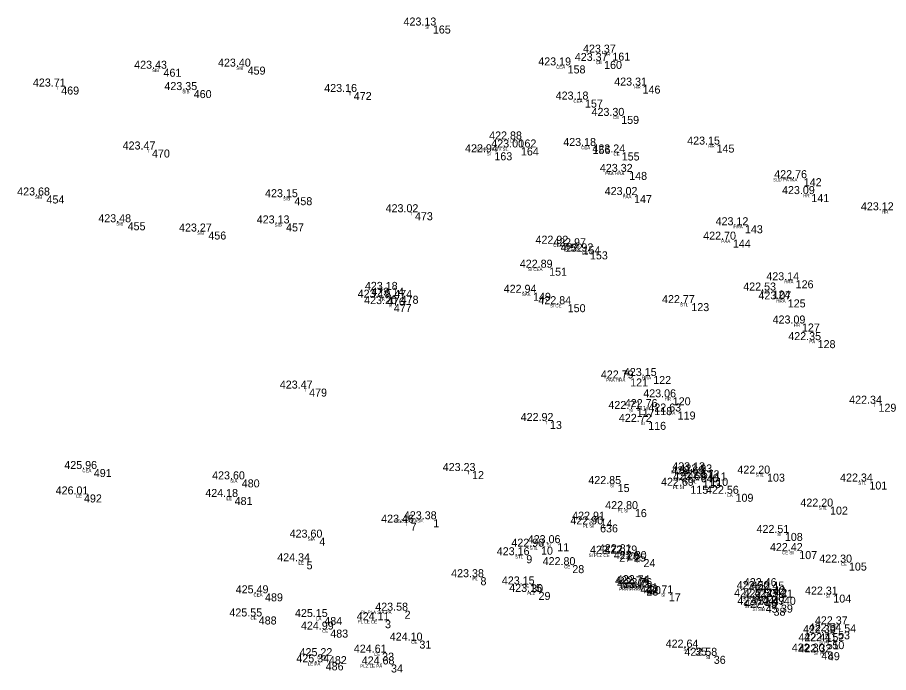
# Model space of a CAD drawing. Extents: x -639373 to -639057, y -1138651 to -1138359.
# Drawn here: x -639183 to -639101.4, y -1138650.6 to -1138589.2 of the extents above; entities that cross this region are included whole.
import ezdxf

# ---------------------------------------------------------------- set-up
doc = ezdxf.new("R2010")
doc.units = 0
for name, color, linetype in [('Vrstva 11', 7, 'Continuous'), ('Vrstva 12', 7, 'Continuous'), ('Vrstva 13', 7, 'Continuous'), ('Vrstva 14', 7, 'Continuous'), ('Vrstva 57', 7, 'Continuous')]:
    doc.layers.add(name, color=color, linetype=linetype)

msp = doc.modelspace()

# ---------------------------------------------------------------- linework, layer by layer
at = {"layer": 'Vrstva 11'}
for p, q in [((-639144.39, -1138589.97), (-639144.39, -1138589.97)), ((-639127.58, -1138592.51), (-639127.58, -1138592.51)), ((-639161.74, -1138593.82), (-639161.74, -1138593.82)), ((-639131.77, -1138593.71), (-639131.77, -1138593.71)), ((-639128.35, -1138593.29), (-639128.35, -1138593.29)), ((-639169.62, -1138594.02), (-639169.62, -1138594.02)), ((-639179.2, -1138595.69), (-639179.2, -1138595.69)), ((-639166.79, -1138596.02), (-639166.79, -1138596.02)), ((-639151.8, -1138596.2), (-639151.8, -1138596.2)), ((-639124.75, -1138595.6), (-639124.75, -1138595.6)), ((-639130.14, -1138596.91), (-639130.14, -1138596.91)), ((-639126.75, -1138598.44), (-639126.75, -1138598.44)), ((-639136.37, -1138600.65), (-639136.37, -1138600.65)), ((-639117.82, -1138601.13), (-639117.82, -1138601.13)), ((-639170.7, -1138601.59), (-639170.7, -1138601.59)), ((-639138.63, -1138601.85), (-639138.63, -1138601.85)), ((-639136.14, -1138601.4), (-639136.14, -1138601.4)), ((-639129.43, -1138601.26), (-639129.43, -1138601.26)), ((-639126.7, -1138601.87), (-639126.7, -1138601.87)), ((-639126, -1138603.69), (-639126, -1138603.69)), ((-639109.65, -1138604.28), (-639109.65, -1138604.28)), ((-639180.58, -1138605.9), (-639180.58, -1138605.9)), ((-639157.36, -1138606.06), (-639157.36, -1138606.06)), ((-639125.55, -1138605.86), (-639125.55, -1138605.86)), ((-639108.94, -1138605.77), (-639108.94, -1138605.77)), ((-639146.07, -1138607.47), (-639146.07, -1138607.47)), ((-639101.55, -1138607.29), (-639101.55, -1138607.29)), ((-639172.98, -1138608.41), (-639172.98, -1138608.41)), ((-639158.14, -1138608.52), (-639158.14, -1138608.52)), ((-639165.42, -1138609.28), (-639165.42, -1138609.28)), ((-639115.16, -1138608.69), (-639115.16, -1138608.69)), ((-639116.29, -1138610.04), (-639116.29, -1138610.04)), ((-639132.03, -1138610.42), (-639132.03, -1138610.42)), ((-639130.37, -1138610.66), (-639130.37, -1138610.66)), ((-639129.68, -1138611.14), (-639129.68, -1138611.14)), ((-639133.5, -1138612.67), (-639133.5, -1138612.67)), ((-639110.41, -1138613.85), (-639110.41, -1138613.85)), ((-639148.01, -1138614.75), (-639148.01, -1138614.75)), ((-639135.01, -1138615.02), (-639135.01, -1138615.02)), ((-639112.57, -1138614.81), (-639112.57, -1138614.81)), ((-639148.69, -1138615.48), (-639148.69, -1138615.48)), ((-639147.41, -1138615.3), (-639147.41, -1138615.3)), ((-639111.15, -1138615.64), (-639111.15, -1138615.64)), ((-639148.05, -1138616.08), (-639148.05, -1138616.08)), ((-639131.76, -1138616.09), (-639131.76, -1138616.09)), ((-639120.18, -1138615.99), (-639120.18, -1138615.99)), ((-639109.82, -1138617.9), (-639109.82, -1138617.9)), ((-639108.35, -1138619.46), (-639108.35, -1138619.46)), ((-639125.91, -1138623.05), (-639125.91, -1138623.05)), ((-639123.75, -1138622.82), (-639123.75, -1138622.82)), ((-639155.98, -1138624), (-639155.98, -1138624)), ((-639121.92, -1138624.82), (-639121.92, -1138624.82)), ((-639102.65, -1138625.42), (-639102.65, -1138625.42)), ((-639125.3, -1138625.91), (-639125.3, -1138625.91)), ((-639123.65, -1138625.74), (-639123.65, -1138625.74)), ((-639121.46, -1138626.15), (-639121.46, -1138626.15)), ((-639133.42, -1138627.04), (-639133.42, -1138627.04)), ((-639124.22, -1138627.12), (-639124.22, -1138627.12)), ((-639176.15, -1138631.54), (-639176.15, -1138631.54)), ((-639140.72, -1138631.73), (-639140.72, -1138631.73)), ((-639119.3, -1138632.04), (-639119.3, -1138632.04)), ((-639119.22, -1138631.66), (-639119.22, -1138631.66)), ((-639118.55, -1138631.86), (-639118.55, -1138631.86)), ((-639113.09, -1138631.97), (-639113.09, -1138631.97)), ((-639162.29, -1138632.51), (-639162.29, -1138632.51)), ((-639127.08, -1138632.95), (-639127.08, -1138632.95)), ((-639119.12, -1138632.58), (-639119.12, -1138632.58)), ((-639118.41, -1138632.37), (-639118.41, -1138632.37)), ((-639103.5, -1138632.71), (-639103.5, -1138632.71)), ((-639120.27, -1138633.11), (-639120.27, -1138633.11)), ((-639116.04, -1138633.86), (-639116.04, -1138633.86)), ((-639177.07, -1138633.92), (-639177.07, -1138633.92)), ((-639162.96, -1138634.16), (-639162.96, -1138634.16)), ((-639125.47, -1138635.3), (-639125.47, -1138635.3)), ((-639107.19, -1138635.06), (-639107.19, -1138635.06)), ((-639144.36, -1138636.25), (-639144.36, -1138636.25)), ((-639128.69, -1138636.29), (-639128.69, -1138636.29)), ((-639146.47, -1138636.57), (-639146.47, -1138636.57)), ((-639128.73, -1138636.73), (-639128.73, -1138636.73)), ((-639111.42, -1138637.53), (-639111.42, -1138637.53)), ((-639155.03, -1138637.97), (-639155.03, -1138637.97)), ((-639132.74, -1138638.49), (-639132.74, -1138638.49)), ((-639134.26, -1138638.82), (-639134.26, -1138638.82)), ((-639126.93, -1138639.48), (-639126.93, -1138639.48)), ((-639126.19, -1138639.34), (-639126.19, -1138639.34)), ((-639125.57, -1138639.46), (-639125.57, -1138639.46)), ((-639110.07, -1138639.23), (-639110.07, -1138639.23)), ((-639156.22, -1138640.19), (-639156.22, -1138640.19)), ((-639135.64, -1138639.62), (-639135.64, -1138639.62)), ((-639124.66, -1138639.98), (-639124.66, -1138639.98)), ((-639105.42, -1138640.31), (-639105.42, -1138640.31)), ((-639131.33, -1138640.55), (-639131.33, -1138640.55)), ((-639139.93, -1138641.68), (-639139.93, -1138641.68)), ((-639135.18, -1138642.36), (-639135.18, -1138642.36)), ((-639124.58, -1138642.35), (-639124.58, -1138642.35)), ((-639124.41, -1138642.24), (-639124.41, -1138642.24)), ((-639124.39, -1138642.65), (-639124.39, -1138642.65)), ((-639124.15, -1138642.52), (-639124.15, -1138642.52)), ((-639113.16, -1138642.8), (-639113.16, -1138642.8)), ((-639112.5, -1138642.52), (-639112.5, -1138642.52)), ((-639111.79, -1138642.84), (-639111.79, -1138642.84)), ((-639160.11, -1138643.19), (-639160.11, -1138643.19)), ((-639134.49, -1138643.06), (-639134.49, -1138643.06)), ((-639122.29, -1138643.19), (-639122.29, -1138643.19)), ((-639113.52, -1138643.51), (-639113.52, -1138643.51)), ((-639112.54, -1138643.55), (-639112.54, -1138643.55)), ((-639111.52, -1138643.52), (-639111.52, -1138643.52)), ((-639106.88, -1138643.31), (-639106.88, -1138643.31)), ((-639113.22, -1138644.26), (-639113.22, -1138644.26)), ((-639111.79, -1138644.25), (-639111.79, -1138644.25)), ((-639147.04, -1138644.82), (-639147.04, -1138644.82)), ((-639112.48, -1138644.54), (-639112.48, -1138644.54)), ((-639160.7, -1138645.36), (-639160.7, -1138645.36)), ((-639154.56, -1138645.41), (-639154.56, -1138645.41)), ((-639148.87, -1138645.71), (-639148.87, -1138645.71)), ((-639105.86, -1138646.1), (-639105.86, -1138646.1)), ((-639154, -1138646.59), (-639154, -1138646.59)), ((-639106.97, -1138646.92), (-639106.97, -1138646.92)), ((-639106.44, -1138646.75), (-639106.44, -1138646.75)), ((-639145.65, -1138647.62), (-639145.65, -1138647.62)), ((-639107.49, -1138647.68), (-639107.49, -1138647.68)), ((-639106.97, -1138647.67), (-639106.97, -1138647.67)), ((-639119.84, -1138648.28), (-639119.84, -1138648.28)), ((-639154.13, -1138649.08), (-639154.13, -1138649.08)), ((-639149.14, -1138648.75), (-639149.14, -1138648.75)), ((-639118.08, -1138649.05), (-639118.08, -1138649.05)), ((-639107.99, -1138648.65), (-639107.99, -1138648.65)), ((-639107.39, -1138648.71), (-639107.39, -1138648.71)), ((-639154.43, -1138649.66), (-639154.43, -1138649.66)), ((-639148.31, -1138649.86), (-639148.31, -1138649.86))]:
    msp.add_line(p, q, dxfattribs=at)

# ---------------------------------------------------------------- texts
at = {"layer": 'Vrstva 12'}
for s, p in [('422.88 ', (-639138.839, -1138600.65)), ('423.00 ', (-639138.639, -1138601.4)), ('423.32 ', (-639128.469, -1138603.69)), ('422.76 ', (-639112.136, -1138604.28)), ('423.02 ', (-639128.019, -1138605.86)), ('423.12 ', (-639117.629, -1138608.69)), ('422.70 ', (-639118.789, -1138610.04)), ('423.14 ', (-639112.879, -1138613.85)), ('422.53 ', (-639115.039, -1138614.81)), ('423.07 ', (-639113.619, -1138615.64)), ('423.09 ', (-639112.289, -1138617.9)), ('422.35 ', (-639110.82, -1138619.46)), ('422.79 ', (-639128.379, -1138623.05)), ('423.15 ', (-639126.22, -1138622.82)), ('423.06 ', (-639124.406, -1138624.82)), ('422.34 ', (-639105.119, -1138625.42)), ('422.76 ', (-639126.136, -1138625.74)), ('422.63 ', (-639123.929, -1138626.15)), ('425.96 ', (-639178.636, -1138631.54)), ('423.13 ', (-639121.689, -1138631.66)), ('422.20 ', (-639115.589, -1138631.97)), ('423.60 ', (-639164.789, -1138632.51)), ('422.34 ', (-639105.969, -1138632.71)), ('426.01 ', (-639179.445, -1138633.92)), ('424.18 ', (-639165.429, -1138634.16)), ('422.56 ', (-639118.526, -1138633.86)), ('422.20 ', (-639109.689, -1138635.06)), ('422.90 ', (-639131.229, -1138636.73)), ('422.51 ', (-639113.795, -1138637.53)), ('423.60 ', (-639157.529, -1138637.97)), ('423.06 ', (-639135.226, -1138638.49)), ('422.77 ', (-639129.399, -1138639.48)), ('422.81 ', (-639128.565, -1138639.34)), ('422.79 ', (-639128.039, -1138639.46)), ('422.42 ', (-639112.539, -1138639.23)), ('424.34 ', (-639158.689, -1138640.19)), ('422.80 ', (-639127.159, -1138639.98)), ('422.30 ', (-639107.919, -1138640.31)), ('422.80 ', (-639133.829, -1138640.55)), ('423.38 ', (-639142.399, -1138641.68)), ('423.15 ', (-639137.65, -1138642.36)), ('422.74 ', (-639127.049, -1138642.35)), ('422.74 ', (-639126.879, -1138642.24)), ('422.72 ', (-639126.859, -1138642.65)), ('422.76 ', (-639126.636, -1138642.52)), ('422.46 ', (-639114.986, -1138642.52)), ('425.49 ', (-639162.579, -1138643.19)), ('423.15 ', (-639136.96, -1138643.06)), ('422.71 ', (-639124.665, -1138643.19)), ('422.51 ', (-639115.895, -1138643.51)), ('422.50 ', (-639115.659, -1138642.8)), ('422.53 ', (-639115.009, -1138643.55)), ('422.45 ', (-639114.26, -1138642.84)), ('422.42 ', (-639113.989, -1138643.52)), ('422.31 ', (-639109.255, -1138643.31)), ('422.51 ', (-639115.595, -1138644.26)), ('422.49 ', (-639114.259, -1138644.25)), ('423.58 ', (-639149.509, -1138644.82)), ('422.45 ', (-639114.95, -1138644.54)), ('425.55 ', (-639163.17, -1138645.36)), ('425.15 ', (-639157.03, -1138645.41)), ('424.11 ', (-639151.245, -1138645.71)), ('424.99 ', (-639156.469, -1138646.59)), ('422.34 ', (-639108.909, -1138646.75)), ('422.37 ', (-639108.329, -1138646.1)), ('424.10 ', (-639148.149, -1138647.62)), ('422.41 ', (-639109.865, -1138647.68)), ('422.39 ', (-639109.439, -1138646.92)), ('422.41 ', (-639109.345, -1138647.67)), ('422.64 ', (-639122.309, -1138648.28)), ('425.22 ', (-639156.599, -1138649.08)), ('424.61 ', (-639151.515, -1138648.75)), ('422.58 ', (-639120.549, -1138649.05)), ('422.30 ', (-639110.489, -1138648.65)), ('422.32 ', (-639109.859, -1138648.71)), ('425.34 ', (-639156.899, -1138649.66)), ('424.68 ', (-639150.779, -1138649.86))]:
    msp.add_text(s, height=0.75, dxfattribs=at).set_placement(p)
at = {"layer": 'Vrstva 13'}
for s, p in [(' 165', (-639144.39, -1138590.72)), (' 161', (-639127.58, -1138593.26)), (' 459', (-639161.74, -1138594.57)), (' 158', (-639131.77, -1138594.46)), (' 160', (-639128.35, -1138594.04)), (' 461', (-639169.62, -1138594.77)), (' 469', (-639179.2, -1138596.44)), (' 460', (-639166.79, -1138596.77)), (' 472', (-639151.8, -1138596.95)), (' 146', (-639124.75, -1138596.35)), (' 157', (-639130.14, -1138597.66)), (' 159', (-639126.75, -1138599.19)), (' 162', (-639136.37, -1138601.4)), (' 145', (-639117.82, -1138601.88)), (' 470', (-639170.7, -1138602.34)), (' 163', (-639138.63, -1138602.6)), (' 164', (-639136.14, -1138602.15)), (' 156', (-639129.43, -1138602.01)), (' 155', (-639126.7, -1138602.62)), (' 148', (-639126, -1138604.44)), (' 142', (-639109.65, -1138605.03)), (' 454', (-639180.58, -1138606.65)), (' 458', (-639157.36, -1138606.81)), (' 147', (-639125.55, -1138606.61)), (' 141', (-639108.94, -1138606.52)), (' 473', (-639146.07, -1138608.22)), (' 455', (-639172.98, -1138609.16)), (' 457', (-639158.14, -1138609.27)), (' 456', (-639165.42, -1138610.03)), (' 143', (-639115.16, -1138609.44)), (' 144', (-639116.29, -1138610.79)), (' 152', (-639132.03, -1138611.17)), (' 154', (-639130.37, -1138611.41)), (' 153', (-639129.68, -1138611.89)), (' 151', (-639133.5, -1138613.42)), (' 126', (-639110.41, -1138614.6)), (' 474', (-639148.01, -1138615.5)), (' 149', (-639135.01, -1138615.77)), (' 124', (-639112.57, -1138615.56)), (' 476', (-639148.69, -1138616.23)), (' 478', (-639147.41, -1138616.05)), (' 125', (-639111.15, -1138616.39)), (' 477', (-639148.05, -1138616.83)), (' 150', (-639131.76, -1138616.84)), (' 123', (-639120.18, -1138616.74)), (' 127', (-639109.82, -1138618.65)), (' 128', (-639108.35, -1138620.21)), (' 121', (-639125.91, -1138623.8)), (' 122', (-639123.75, -1138623.57)), (' 479', (-639155.98, -1138624.75)), (' 120', (-639121.92, -1138625.57)), (' 129', (-639102.65, -1138626.17)), (' 117', (-639125.3, -1138626.66)), (' 118', (-639123.65, -1138626.49)), (' 119', (-639121.46, -1138626.9)), (' 13', (-639133.42, -1138627.79)), (' 116', (-639124.22, -1138627.87)), (' 491', (-639176.15, -1138632.29)), (' 12', (-639140.72, -1138632.48)), (' 640', (-639119.3, -1138632.79)), (' 112', (-639119.22, -1138632.41)), (' 111', (-639118.55, -1138632.61)), (' 103', (-639113.09, -1138632.72)), (' 480', (-639162.29, -1138633.26)), (' 15', (-639127.08, -1138633.7)), (' 113', (-639119.12, -1138633.33)), (' 110', (-639118.41, -1138633.12)), (' 101', (-639103.5, -1138633.46)), (' 115', (-639120.27, -1138633.86)), (' 109', (-639116.04, -1138634.61)), (' 492', (-639177.07, -1138634.67)), (' 481', (-639162.96, -1138634.91)), (' 16', (-639125.47, -1138636.05)), (' 102', (-639107.19, -1138635.81)), (' 1', (-639144.36, -1138637)), (' 14', (-639128.69, -1138637.04)), (' 7', (-639146.47, -1138637.32)), (' 636', (-639128.73, -1138637.48)), (' 108', (-639111.42, -1138638.28)), (' 4', (-639155.03, -1138638.72)), (' 11', (-639132.74, -1138639.24)), (' 10', (-639134.26, -1138639.57)), (' 27', (-639126.93, -1138640.23)), (' 26', (-639126.19, -1138640.09)), (' 25', (-639125.57, -1138640.21)), (' 107', (-639110.07, -1138639.98)), (' 5', (-639156.22, -1138640.94)), (' 9', (-639135.64, -1138640.37)), (' 24', (-639124.66, -1138640.73)), (' 105', (-639105.42, -1138641.06)), (' 28', (-639131.33, -1138641.3)), (' 8', (-639139.93, -1138642.43)), (' 30', (-639135.18, -1138643.11)), (' 22', (-639124.58, -1138643.1)), (' 21', (-639124.41, -1138642.99)), (' 23', (-639124.39, -1138643.4)), (' 20', (-639124.15, -1138643.27)), (' 43', (-639113.16, -1138643.55)), (' 42', (-639112.5, -1138643.27)), (' 41', (-639111.79, -1138643.59)), (' 489', (-639160.11, -1138643.94)), (' 29', (-639134.49, -1138643.81)), (' 17', (-639122.29, -1138643.94)), (' 44', (-639113.52, -1138644.26)), (' 47', (-639112.54, -1138644.3)), (' 40', (-639111.52, -1138644.27)), (' 104', (-639106.88, -1138644.06)), (' 45', (-639113.22, -1138645.01)), (' 39', (-639111.79, -1138645)), (' 2', (-639147.04, -1138645.57)), (' 38', (-639112.48, -1138645.29)), (' 488', (-639160.7, -1138646.11)), (' 484', (-639154.56, -1138646.16)), (' 3', (-639148.87, -1138646.46)), (' 54', (-639105.86, -1138646.85)), (' 483', (-639154, -1138647.34)), (' 52', (-639106.97, -1138647.67)), (' 53', (-639106.44, -1138647.5)), (' 31', (-639145.65, -1138648.37)), (' 51', (-639107.49, -1138648.43)), (' 50', (-639106.97, -1138648.42)), (' 35', (-639119.84, -1138649.03)), (' 482', (-639154.13, -1138649.83)), (' 33', (-639149.14, -1138649.5)), (' 36', (-639118.08, -1138649.8)), (' 48', (-639107.99, -1138649.4)), (' 49', (-639107.39, -1138649.46)), (' 486', (-639154.43, -1138650.41)), (' 34', (-639148.31, -1138650.61))]:
    msp.add_text(s, height=0.75, dxfattribs=at).set_placement(p)
at = {"layer": 'Vrstva 14'}
for s, p in [('423.13 ', (-639146.859, -1138589.97)), ('423.37 ', (-639130.049, -1138592.51)), ('423.40 ', (-639164.239, -1138593.82)), ('423.19 ', (-639134.239, -1138593.71)), ('423.37 ', (-639130.819, -1138593.29)), ('423.43 ', (-639172.089, -1138594.02)), ('423.71 ', (-639181.575, -1138595.69)), ('423.35 ', (-639169.26, -1138596.02)), ('423.16 ', (-639154.286, -1138596.2)), ('423.31 ', (-639127.125, -1138595.6)), ('423.18 ', (-639132.609, -1138596.91)), ('423.30 ', (-639129.249, -1138598.44)), ('423.15 ', (-639120.29, -1138601.13)), ('423.47 ', (-639173.169, -1138601.59)), ('422.94 ', (-639141.099, -1138601.85)), ('423.18 ', (-639131.899, -1138601.26)), ('423.24 ', (-639129.169, -1138601.87)), ('423.68 ', (-639183.049, -1138605.9)), ('423.15 ', (-639159.83, -1138606.06)), ('423.09 ', (-639111.409, -1138605.77)), ('423.02 ', (-639148.539, -1138607.47)), ('423.12 ', (-639104.019, -1138607.29)), ('423.48 ', (-639175.449, -1138608.41)), ('423.13 ', (-639160.609, -1138608.52)), ('423.27 ', (-639167.889, -1138609.28)), ('422.92 ', (-639134.499, -1138610.42)), ('422.97 ', (-639132.839, -1138610.66)), ('422.92 ', (-639132.149, -1138611.14)), ('422.89 ', (-639135.969, -1138612.67)), ('423.18 ', (-639150.479, -1138614.75)), ('422.94 ', (-639137.479, -1138615.02)), ('423.19 ', (-639151.159, -1138615.48)), ('423.14 ', (-639149.879, -1138615.3)), ('423.20 ', (-639150.549, -1138616.08)), ('422.84 ', (-639134.229, -1138616.09)), ('422.77 ', (-639122.649, -1138615.99)), ('423.47 ', (-639158.449, -1138624)), ('422.71 ', (-639127.675, -1138625.91)), ('422.92 ', (-639135.889, -1138627.04)), ('422.72 ', (-639126.689, -1138627.12)), ('423.23 ', (-639143.189, -1138631.73)), ('422.69 ', (-639121.769, -1138632.04)), ('422.93 ', (-639121.019, -1138631.86)), ('422.85 ', (-639129.55, -1138632.95)), ('422.69 ', (-639121.589, -1138632.58)), ('422.57 ', (-639120.879, -1138632.37)), ('422.69 ', (-639122.739, -1138633.11)), ('422.80 ', (-639127.969, -1138635.3)), ('423.38 ', (-639146.829, -1138636.25)), ('423.46 ', (-639148.956, -1138636.57)), ('422.91 ', (-639131.065, -1138636.29)), ('422.90 ', (-639136.759, -1138638.82)), ('423.16 ', (-639138.126, -1138639.62))]:
    msp.add_text(s, height=0.75, dxfattribs=at).set_placement(p)
at = {"layer": 'Vrstva 57'}
for s, p in [('SI', (-639144.828, -1138590.27)), ('HR', (-639128.069, -1138592.81)), ('SIB', (-639162.529, -1138594.12)), ('CEA', (-639132.57, -1138594.01)), ('CE', (-639128.838, -1138593.59)), ('SIB', (-639170.409, -1138594.32)), ('T', (-639179.4, -1138595.99)), ('SIB', (-639167.579, -1138596.32)), ('T', (-639152, -1138596.5)), ('HR', (-639125.239, -1138595.9)), ('CEA', (-639130.94, -1138597.21)), ('CE', (-639127.238, -1138598.74)), ('LA', (-639136.87, -1138600.95)), ('HR', (-639118.309, -1138601.43)), ('T', (-639170.9, -1138601.89)), ('SPMR - KOV.SL.', (-639140.139, -1138601.7)), ('SI', (-639139.068, -1138602.15)), ('CEA', (-639130.23, -1138601.56)), ('CE', (-639127.188, -1138602.17)), ('PAA HRA', (-639128, -1138603.99)), ('SLD PATKA', (-639112.25, -1138604.58)), ('SIB', (-639181.369, -1138606.2)), ('SIB', (-639158.149, -1138606.36)), ('PAA', (-639126.35, -1138606.16)), ('HR', (-639109.429, -1138606.07)), ('T', (-639146.27, -1138607.77)), ('HR', (-639102.039, -1138607.59)), ('SIB', (-639173.769, -1138608.71)), ('SIB', (-639158.929, -1138608.82)), ('SIB', (-639166.209, -1138609.58)), ('HRA', (-639115.96, -1138608.99)), ('PAA', (-639117.09, -1138610.34)), ('CEA', (-639132.83, -1138610.72)), ('STERK', (-639131.745, -1138610.96)), ('CE', (-639130.167, -1138611.44)), ('SI CEA', (-639135.2, -1138612.97)), ('HRA', (-639111.21, -1138614.15)), ('K KA', (-639149.11, -1138615.05)), ('SAK', (-639135.785, -1138615.32)), ('PAA', (-639113.37, -1138615.11)), ('K', (-639148.865, -1138615.78)), ('K KA', (-639148.51, -1138615.6)), ('HRA', (-639111.95, -1138615.94)), ('K', (-639148.225, -1138616.38)), ('SI CE', (-639133.147, -1138616.39)), ('STL', (-639120.955, -1138616.29)), ('HR', (-639110.309, -1138618.2)), ('PA', (-639108.85, -1138619.76)), ('PAA HRA', (-639127.91, -1138623.35)), ('HRA', (-639124.55, -1138623.12)), ('T', (-639156.18, -1138624.3)), ('HR', (-639122.409, -1138625.12)), ('T', (-639102.85, -1138625.72)), ('SI', (-639125.738, -1138626.21)), ('PA HR', (-639125.039, -1138626.04)), ('PA', (-639121.96, -1138626.45)), ('T', (-639133.62, -1138627.34)), ('SI', (-639124.658, -1138627.42)), ('CEA', (-639176.95, -1138631.84)), ('T', (-639140.92, -1138632.03)), ('STL - KER', (-639121.809, -1138631.96)), ('PLZ', (-639120.089, -1138632.34)), ('PLZA', (-639119.65, -1138632.16)), ('STL', (-639113.865, -1138632.27)), ('SIA', (-639163.09, -1138632.81)), ('SI', (-639127.518, -1138633.25)), ('SI PLZ PLZA', (-639121.61, -1138632.67)), ('PLZ PL', (-639120.795, -1138632.88)), ('STL', (-639104.275, -1138633.01)), ('PL SI', (-639121.608, -1138633.41)), ('LA', (-639116.54, -1138634.16)), ('CE', (-639177.557, -1138634.22)), ('LE', (-639163.448, -1138634.46)), ('PL SI', (-639126.808, -1138635.6)), ('STL', (-639107.965, -1138635.36)), ('ROZBITY ASF.', (-639147.759, -1138636.55)), ('STL', (-639129.465, -1138636.59)), ('T', (-639146.67, -1138636.87)), ('PL SI', (-639130.068, -1138637.03)), ('SI', (-639111.858, -1138637.83)), ('SIA', (-639155.83, -1138638.27)), ('PL SI', (-639134.078, -1138638.79)), ('STL', (-639135.035, -1138639.12)), ('SI PLZ CE', (-639129.517, -1138639.78)), ('SI', (-639126.628, -1138639.64)), ('SI', (-639126.008, -1138639.76)), ('CE SI', (-639111.408, -1138639.53)), ('LE', (-639156.708, -1138640.49)), ('STL', (-639136.415, -1138639.92)), ('SI', (-639125.098, -1138640.28)), ('CE', (-639105.907, -1138640.61)), ('CE', (-639131.818, -1138640.85)), ('PL', (-639140.405, -1138641.98)), ('CE', (-639135.667, -1138642.66)), ('PRR PRRA', (-639126.69, -1138642.95)), ('PRR PRRA', (-639126.45, -1138642.82)), ('PRR', (-639125.369, -1138642.65)), ('PRR', (-639125.199, -1138642.54)), ('SI', (-639113.598, -1138643.1)), ('SI', (-639112.938, -1138642.82)), ('SI', (-639112.228, -1138643.14)), ('CEA', (-639160.91, -1138643.49)), ('PLZ', (-639135.279, -1138643.36)), ('SI', (-639122.728, -1138643.49)), ('SLB NN 2X', (-639115.128, -1138643.85)), ('SI', (-639113.958, -1138643.81)), ('SI', (-639111.958, -1138643.82)), ('SI', (-639107.318, -1138643.61)), ('SI SIB', (-639114.909, -1138644.56)), ('SI', (-639112.228, -1138644.55)), ('PL PLA SIA PA', (-639150.84, -1138645.12)), ('SI SIB', (-639114.169, -1138644.84)), ('CE', (-639161.188, -1138645.66)), ('LA', (-639155.06, -1138645.71)), ('PL LE CE', (-639151.157, -1138646.01)), ('PL SI', (-639107.198, -1138646.4)), ('CE', (-639154.488, -1138646.89)), ('SI', (-639107.408, -1138647.22)), ('PL', (-639106.915, -1138647.05)), ('CE', (-639146.138, -1138647.92)), ('SI', (-639107.928, -1138647.98)), ('PL', (-639107.445, -1138647.97)), ('SAV', (-639120.64, -1138648.58)), ('CEA', (-639154.93, -1138649.38)), ('CE', (-639149.628, -1138649.05)), ('SI', (-639118.518, -1138649.35)), ('SI', (-639108.428, -1138648.95)), ('PL', (-639107.865, -1138649.01)), ('LE PA', (-639155.83, -1138649.96)), ('PLZ LE PA', (-639150.91, -1138650.16))]:
    msp.add_text(s, height=0.3, dxfattribs=at).set_placement(p)

doc.saveas('drawing.dxf')
